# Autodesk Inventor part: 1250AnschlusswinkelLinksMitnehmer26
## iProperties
Category: PARTsolutions
Created: 2011-08
Part Number: 1250AnschlusswinkelLinksMitnehmer26
Catalog Web Link: www.cadenas.de
Description: 1250 Anschlusswinkel links Mitnehmer - Anschlusswinkel links Mitnehmer
Document SubType Name: Modeling
Designer: PARTsolutions
Density: 1 g/cm^3
Mass: 94.6561 g
Surface Area: 415.473 cm^2
Volume: 94.6561 cm^3
NB: 1250AnschlusswinkelLinksMitnehmer26
NN: 1250 Anschlusswinkel links Mitnehmer
NT: Anschlusswinkel links Mitnehmer
NBSYN: 1250AnschlusswinkelLinksMitnehmer26
LINA: 1250AnschlusswinkelLinksMitnehmer26
BEST: 1250AnschlusswinkelLinksMitnehmer
MA: 2
STEGV: 6
PIN: 18.800
KT: DUMMY
SUPPLIER: Kabelschlepp
ARTICLENO: 1250AnschlusswinkelLinksMitnehmer26
BOMINFO: 1250AnschlusswinkelLinksMitnehmer26
CREATOR: CADENAS GmbH
PSOL_IDENT_0: {\\10.0.0.251\ps_data\23d-libs\kabelschlepp\4_eketten_st\parts\1250_anschlusswinkel_links_m.prj},250
PSOL_IDENT_1: {VTYP=3D},{NB=1250AnschlusswinkelLinksMitnehmer26},{LINA=1250AnschlusswinkelLinksMitnehmer26},{NN=1
PSOL_IDENT_2: 250 Anschlusswinkel links Mitnehmer},{DATE=31.05.2007 07:52:20},{GEOMDATE=20.03.2007 12:43:00},{VERS
PSOL_IDENT_3: ION=},{LINEID=10},{LINESUBID=-1},{WBVAR=MA,STEGV}  {NB=1250AnschlusswinkelLinksMitnehmer26},{LINA=12
PSOL_IDENT_4: 50AnschlusswinkelLinksMitnehmer26},{KT=DUMMY},{BEST=1250AnschlusswinkelLinksMitnehmer},{MA=2},{STEGV
PSOL_IDENT_5: =6},{PIN=18.8}
Title: 1250AnschlusswinkelLinksMitnehmer26
Author: Cadenas PARTsolutions
Comments: Anschlusswinkel links Mitnehmer
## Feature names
1. Extrusion1
2. Extrusion2
3. Extrusion3
4. Extrusion4
5. Extrusion5
6. Revolution1
7. Revolution2
8. Extrusion6
